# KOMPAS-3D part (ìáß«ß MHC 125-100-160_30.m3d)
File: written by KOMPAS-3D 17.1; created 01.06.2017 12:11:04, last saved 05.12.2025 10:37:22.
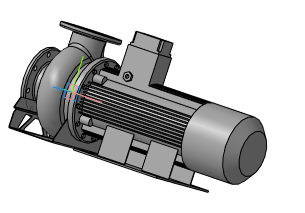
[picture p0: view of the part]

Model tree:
1. Операция без истории:4

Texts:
  ООО АДЛ ГРУПП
